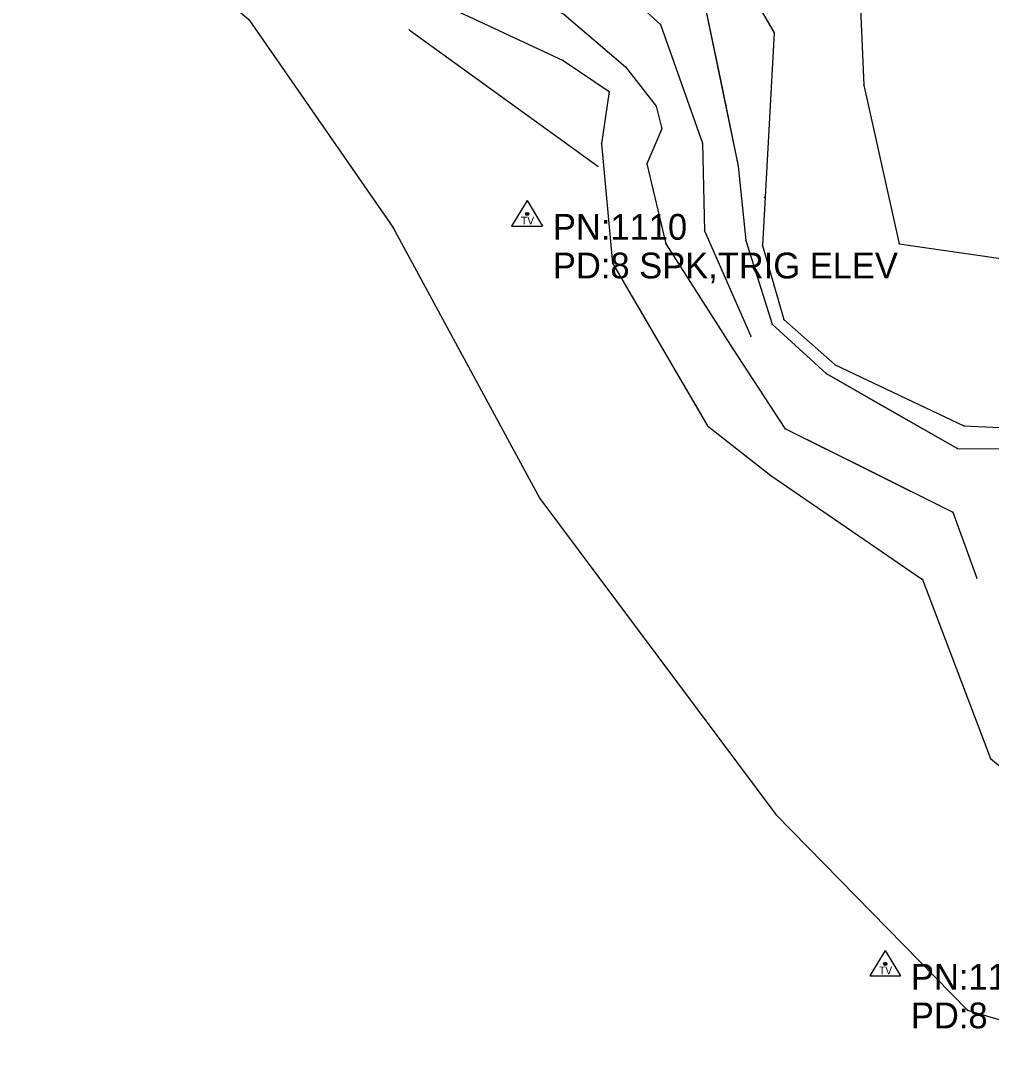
# Model space of a CAD drawing. Extents: x -99999 to 591807, y -99999 to 347168.
# Drawn here: x 588350.5 to 588538.7, y 344868.6 to 345068.8 of the extents above; entities that cross this region are included whole.
import ezdxf

# ---------------------------------------------------------------- set-up
doc = ezdxf.new("R2010")
doc.units = 0
for name, color, linetype in [('S_BREAKLINE', 7, 'Continuous'), ('S_DRG_PT_SYM', 7, 'Continuous'), ('S_GRD_PT_SYM', 7, 'Continuous'), ('S_SECONDARY_CTL', 7, 'Continuous'), ('S_SECONDARY_CTL_ANNOT', 7, 'Continuous'), ('S_STREAM', 7, 'Continuous')]:
    doc.layers.add(name, color=color, linetype=linetype)

msp = doc.modelspace()

# ---------------------------------------------------------------- linework, layer by layer
at = {"layer": 'S_BREAKLINE'}
for points in [[(588235.94, 344982.86), (588208.37, 345000.41), (588217.32, 345040.49), (588224.71, 345087.25), (588242.03, 345109.14), (588258.57, 345128.16), (588275.14, 345149.4), (588293.08, 345174.26), (588318.74, 345191.92), (588364.7, 345201.57), (588418.81, 345183.14), (588457.6, 345182.95), (588490.37, 345161.7), (588511.98, 345102.51), (588513.98, 345056.26), (588520.82, 345025.49), (588548.64, 345021.47), (588563.11, 345047.59), (588608.01, 345055.64)], [(588241.79, 344998.22), (588230.75, 345014.34), (588234.41, 345036.47), (588251.81, 345073.52), (588263.76, 345090.67), (588277.7, 345115.07), (588291.38, 345129.59), (588310.56, 345146.9), (588336.04, 345156.17), (588376.69, 345158.12), (588409.44, 345149.59), (588422.89, 345130.25), (588439.21, 345121.9), (588464.81, 345100.35), (588488.08, 345081.15), (588496.59, 345066.4), (588494.34, 345025.15), (588498.47, 345010.76), (588508.41, 345001.98), (588533.39, 344990.16), (588579.62, 344988.03), (588607.58, 345002.1)], [(588342.93, 345124.15), (588361.5, 345126.13), (588391.77, 345106.15), (588403.87, 345085.31), (588455.72, 345061.01), (588464.59, 345055.04), (588463.13, 345044.9), (588465.23, 345021.73), (588483.68, 344990.17), (588495.94, 344980.54), (588525.4, 344960.33), (588538.54, 344925.61), (588555.91, 344911.33), (588562.59, 344905.26), (588609.87, 344912.87), (588643.73, 344923.05), (588654.31, 344931.44), (588666.76, 344967), (588674.22, 344955.37), (588686.58, 344954.82), (588685.3, 344962.67), (588669.71, 344982.82), (588662.5, 344988.18), (588669.96, 344999.57)], [(588351.97, 345105.67), (588394.75, 345069), (588422.63, 345028.7), (588451.14, 344976.07), (588496.93, 344914.75), (588534.1, 344876.77), (588561.64, 344868.59), (588621.42, 344887.88), (588675.83, 344912.22), (588695.28, 344933.47)], [(588443.14, 345099.18), (588458.7, 345082.45), (588474.57, 345068.02), (588482.72, 345045), (588483.12, 345028.01), (588492.09, 345007.54)], [(588425.85, 345067), (588462.43, 345040.54)]]:
    msp.add_lwpolyline(points, dxfattribs=at)
at = {"layer": 'S_DRG_PT_SYM'}
for points in [[(588467.81, 345059.79), (588467.85, 345059.82), (588467.81, 345059.79), (588467.78, 345059.83), (588467.81, 345059.79), (588467.77, 345059.76), (588467.81, 345059.79), (588467.84, 345059.75)], [(588473.73, 345052.15), (588473.78, 345052.17), (588473.73, 345052.15), (588473.72, 345052.2), (588473.73, 345052.15), (588473.68, 345052.14), (588473.73, 345052.15), (588473.74, 345052.11)], [(588474.83, 345047.75), (588474.88, 345047.73), (588474.83, 345047.75), (588474.85, 345047.79), (588474.83, 345047.75), (588474.79, 345047.77), (588474.83, 345047.75), (588474.81, 345047.7)], [(588471.91, 345040.97), (588471.96, 345040.98), (588471.91, 345040.97), (588471.9, 345041.02), (588471.91, 345040.97), (588471.86, 345040.96), (588471.91, 345040.97), (588471.92, 345040.92)], [(588489.64, 345040.56), (588489.69, 345040.56), (588489.64, 345040.56), (588489.64, 345040.61), (588489.64, 345040.56), (588489.59, 345040.55), (588489.64, 345040.56), (588489.65, 345040.51)], [(588475.57, 345025.49), (588475.61, 345025.52), (588475.57, 345025.49), (588475.54, 345025.53), (588475.57, 345025.49), (588475.52, 345025.46), (588475.57, 345025.49), (588475.59, 345025.45)], [(588491.13, 345026.13), (588491.18, 345026.14), (588491.13, 345026.13), (588491.12, 345026.18), (588491.13, 345026.13), (588491.09, 345026.11), (588491.13, 345026.13), (588491.15, 345026.08)], [(588496.2, 345009.85), (588496.23, 345009.88), (588496.2, 345009.85), (588496.16, 345009.88), (588496.2, 345009.85), (588496.16, 345009.81), (588496.2, 345009.85), (588496.23, 345009.81)], [(588488.57, 345005.12), (588488.61, 345005.15), (588488.57, 345005.12), (588488.54, 345005.17), (588488.57, 345005.12), (588488.53, 345005.1), (588488.57, 345005.12), (588488.6, 345005.08)], [(588506.71, 345000.28), (588506.73, 345000.33), (588506.71, 345000.28), (588506.67, 345000.31), (588506.71, 345000.28), (588506.68, 345000.24), (588506.71, 345000.28), (588506.75, 345000.26)], [(588498.65, 344989.67), (588498.67, 344989.72), (588498.65, 344989.67), (588498.61, 344989.69), (588498.65, 344989.67), (588498.63, 344989.63), (588498.65, 344989.67), (588498.69, 344989.65)], [(588532.17, 344985.73), (588532.17, 344985.78), (588532.17, 344985.73), (588532.12, 344985.73), (588532.17, 344985.73), (588532.17, 344985.68), (588532.17, 344985.73), (588532.22, 344985.73)], [(588531.26, 344973.41), (588531.31, 344973.42), (588531.26, 344973.41), (588531.24, 344973.45), (588531.26, 344973.41), (588531.21, 344973.39), (588531.26, 344973.41), (588531.28, 344973.36)], [(588535.88, 344960.6), (588535.93, 344960.62), (588535.88, 344960.6), (588535.87, 344960.65), (588535.88, 344960.6), (588535.84, 344960.58), (588535.88, 344960.6), (588535.9, 344960.55)]]:
    msp.add_lwpolyline(points, close=True, dxfattribs=at)
at = {"layer": 'S_GRD_PT_SYM'}
for points in [[(588425.85, 345067), (588425.88, 345067.04), (588425.85, 345067), (588425.81, 345067.03), (588425.85, 345067), (588425.83, 345066.96), (588425.85, 345067), (588425.9, 345066.97)], [(588474.57, 345068.02), (588474.61, 345068.04), (588474.57, 345068.02), (588474.55, 345068.07), (588474.57, 345068.02), (588474.52, 345068), (588474.57, 345068.02), (588474.58, 345067.97)], [(588496.59, 345066.4), (588496.64, 345066.39), (588496.59, 345066.4), (588496.59, 345066.45), (588496.59, 345066.4), (588496.54, 345066.4), (588496.59, 345066.4), (588496.59, 345066.35)], [(588455.72, 345061.01), (588455.75, 345061.05), (588455.72, 345061.01), (588455.68, 345061.04), (588455.72, 345061.01), (588455.69, 345060.97), (588455.72, 345061.01), (588455.76, 345060.98)], [(588464.59, 345055.04), (588464.64, 345055.03), (588464.59, 345055.04), (588464.6, 345055.09), (588464.59, 345055.04), (588464.54, 345055.05), (588464.59, 345055.04), (588464.58, 345054.99)], [(588513.98, 345056.26), (588514.02, 345056.27), (588513.98, 345056.26), (588513.97, 345056.31), (588513.98, 345056.26), (588513.93, 345056.25), (588513.98, 345056.26), (588513.99, 345056.21)], [(588463.13, 345044.9), (588463.18, 345044.91), (588463.13, 345044.9), (588463.13, 345044.95), (588463.13, 345044.9), (588463.08, 345044.9), (588463.13, 345044.9), (588463.14, 345044.85)], [(588482.72, 345045), (588482.77, 345045), (588482.72, 345045), (588482.72, 345045.05), (588482.72, 345045), (588482.67, 345045), (588482.72, 345045), (588482.72, 345044.95)], [(588462.43, 345040.54), (588462.46, 345040.58), (588462.43, 345040.54), (588462.39, 345040.57), (588462.43, 345040.54), (588462.4, 345040.5), (588462.43, 345040.54), (588462.47, 345040.51)], [(588494.75, 345034.48), (588494.75, 345034.53), (588494.75, 345034.48), (588494.7, 345034.48), (588494.75, 345034.48), (588494.75, 345034.43), (588494.75, 345034.48), (588494.8, 345034.48)], [(588422.63, 345028.7), (588422.68, 345028.72), (588422.63, 345028.7), (588422.61, 345028.74), (588422.63, 345028.7), (588422.59, 345028.68), (588422.63, 345028.7), (588422.66, 345028.66)], [(588483.12, 345028.01), (588483.17, 345028.03), (588483.12, 345028.01), (588483.1, 345028.06), (588483.12, 345028.01), (588483.08, 345027.99), (588483.12, 345028.01), (588483.14, 345027.97)], [(588494.34, 345025.15), (588494.39, 345025.17), (588494.34, 345025.15), (588494.33, 345025.2), (588494.34, 345025.15), (588494.29, 345025.14), (588494.34, 345025.15), (588494.35, 345025.11)], [(588520.82, 345025.49), (588520.83, 345025.53), (588520.82, 345025.49), (588520.77, 345025.49), (588520.82, 345025.49), (588520.81, 345025.44), (588520.82, 345025.49), (588520.87, 345025.48)], [(588465.23, 345021.73), (588465.27, 345021.76), (588465.23, 345021.73), (588465.2, 345021.77), (588465.23, 345021.73), (588465.19, 345021.7), (588465.23, 345021.73), (588465.25, 345021.69)], [(588498.47, 345010.76), (588498.5, 345010.8), (588498.47, 345010.76), (588498.43, 345010.8), (588498.47, 345010.76), (588498.43, 345010.72), (588498.47, 345010.76), (588498.5, 345010.73)], [(588492.09, 345007.54), (588492.13, 345007.56), (588492.09, 345007.54), (588492.07, 345007.58), (588492.09, 345007.54), (588492.04, 345007.52), (588492.09, 345007.54), (588492.11, 345007.49)], [(588508.41, 345001.98), (588508.44, 345002.02), (588508.41, 345001.98), (588508.37, 345002), (588508.41, 345001.98), (588508.39, 345001.93), (588508.41, 345001.98), (588508.46, 345001.96)], [(588483.68, 344990.17), (588483.71, 344990.21), (588483.68, 344990.17), (588483.64, 344990.2), (588483.68, 344990.17), (588483.65, 344990.13), (588483.68, 344990.17), (588483.72, 344990.13)], [(588533.39, 344990.16), (588533.39, 344990.21), (588533.39, 344990.16), (588533.34, 344990.16), (588533.39, 344990.16), (588533.39, 344990.11), (588533.39, 344990.16), (588533.44, 344990.16)], [(588495.94, 344980.54), (588495.97, 344980.58), (588495.94, 344980.54), (588495.9, 344980.57), (588495.94, 344980.54), (588495.91, 344980.5), (588495.94, 344980.54), (588495.98, 344980.51)], [(588451.14, 344976.07), (588451.18, 344976.1), (588451.14, 344976.07), (588451.11, 344976.11), (588451.14, 344976.07), (588451.1, 344976.04), (588451.14, 344976.07), (588451.17, 344976.03)], [(588525.4, 344960.33), (588525.45, 344960.35), (588525.4, 344960.33), (588525.38, 344960.38), (588525.4, 344960.33), (588525.36, 344960.32), (588525.4, 344960.33), (588525.42, 344960.29)], [(588538.54, 344925.61), (588538.57, 344925.65), (588538.54, 344925.61), (588538.5, 344925.64), (588538.54, 344925.61), (588538.51, 344925.57), (588538.54, 344925.61), (588538.58, 344925.58)], [(588496.93, 344914.75), (588496.97, 344914.79), (588496.93, 344914.75), (588496.9, 344914.79), (588496.93, 344914.75), (588496.9, 344914.72), (588496.93, 344914.75), (588496.97, 344914.72)], [(588534.1, 344876.77), (588534.12, 344876.82), (588534.1, 344876.77), (588534.06, 344876.79), (588534.1, 344876.77), (588534.09, 344876.72), (588534.1, 344876.77), (588534.15, 344876.76)]]:
    msp.add_lwpolyline(points, close=True, dxfattribs=at)
at = {"layer": 'S_SECONDARY_CTL'}
for p, q in [((588448.71, 345033.87), (588445.7, 345028.91)), ((588448.71, 345033.87), (588451.66, 345028.91)), ((588445.7, 345028.91), (588451.66, 345028.91)), ((588518.14, 344888.37), (588515.13, 344883.42)), ((588518.14, 344888.37), (588521.09, 344883.42)), ((588515.13, 344883.42), (588521.09, 344883.42))]:
    msp.add_line(p, q, dxfattribs=at)
for centre, radius in [((588448.71, 345031.26), 0.311), ((588448.71, 345031.26), 0.183), ((588448.71, 345031.26), 0.103), ((588518.14, 344885.76), 0.311), ((588518.14, 344885.76), 0.183), ((588518.14, 344885.76), 0.103)]:
    msp.add_circle(centre, radius, dxfattribs=at)
at = {"layer": 'S_STREAM'}
for points in [[(588336.3, 345129.42), (588361.74, 345127.97), (588387.1, 345127.57), (588398.98, 345129.63), (588410.38, 345121), (588426.49, 345112.53), (588432.77, 345098.31), (588441.11, 345086.11), (588443.5, 345076.36), (588455.81, 345070.06), (588467.81, 345059.79), (588473.73, 345052.15), (588474.83, 345047.75), (588471.91, 345040.97), (588475.57, 345025.49), (588488.57, 345005.12), (588498.65, 344989.67), (588531.26, 344973.41), (588535.88, 344960.6)], [(588349.02, 345128.7), (588361.74, 345127.97), (588374.42, 345127.77), (588387.1, 345127.57), (588398.98, 345129.63), (588410.38, 345121), (588426.49, 345112.53), (588432.77, 345098.31), (588441.11, 345086.11), (588443.5, 345076.36), (588455.81, 345070.06), (588467.81, 345059.79), (588473.73, 345052.15), (588474.83, 345047.75), (588471.91, 345040.97), (588475.57, 345025.49), (588488.57, 345005.12), (588498.65, 344989.67), (588514.95, 344981.54), (588531.26, 344973.41), (588535.88, 344960.6)], [(588482.71, 345073.99), (588489.64, 345040.56), (588491.13, 345026.13), (588496.2, 345009.85), (588506.71, 345000.28), (588532.17, 344985.73), (588567.15, 344985.58), (588583.13, 344983.03), (588631.8, 345011.02), (588655.22, 345025.34), (588665.76, 345030.45), (588690.1, 345042.42), (588700.08, 345055.13), (588707.87, 345064.11), (588739.08, 345094.75)], [(588482.71, 345073.99), (588486.18, 345057.27), (588489.64, 345040.56), (588491.13, 345026.13), (588496.2, 345009.85), (588506.71, 345000.28), (588519.44, 344993.01), (588532.17, 344985.73), (588549.66, 344985.66), (588567.15, 344985.58), (588583.13, 344983.03), (588595.3, 344990.03), (588607.47, 344997.02), (588619.63, 345004.02), (588631.8, 345011.02), (588643.51, 345018.18), (588655.22, 345025.34), (588665.76, 345030.45), (588677.93, 345036.44), (588690.1, 345042.42), (588700.08, 345055.13), (588707.87, 345064.11), (588723.47, 345079.43)]]:
    msp.add_lwpolyline(points, dxfattribs=at)

# ---------------------------------------------------------------- texts
at = {"layer": 'S_SECONDARY_CTL'}
for p in [(588447.5, 345029.24), (588516.93, 344883.75)]:
    msp.add_text('TV', height=1.5, rotation=360, dxfattribs=at).set_placement(p)
at = {"layer": 'S_SECONDARY_CTL_ANNOT'}
for s, p in [('PN:1110', (588453.71, 345026.26)), ('PD:8 SPK,TRIG ELEV', (588453.71, 345018.76)), ('PN:1109', (588523.14, 344880.76)), ('PD:8 SPK,TRIG ELEV', (588523.14, 344873.26))]:
    msp.add_text(s, height=5, dxfattribs=at).set_placement(p)

doc.saveas('drawing.dxf')
